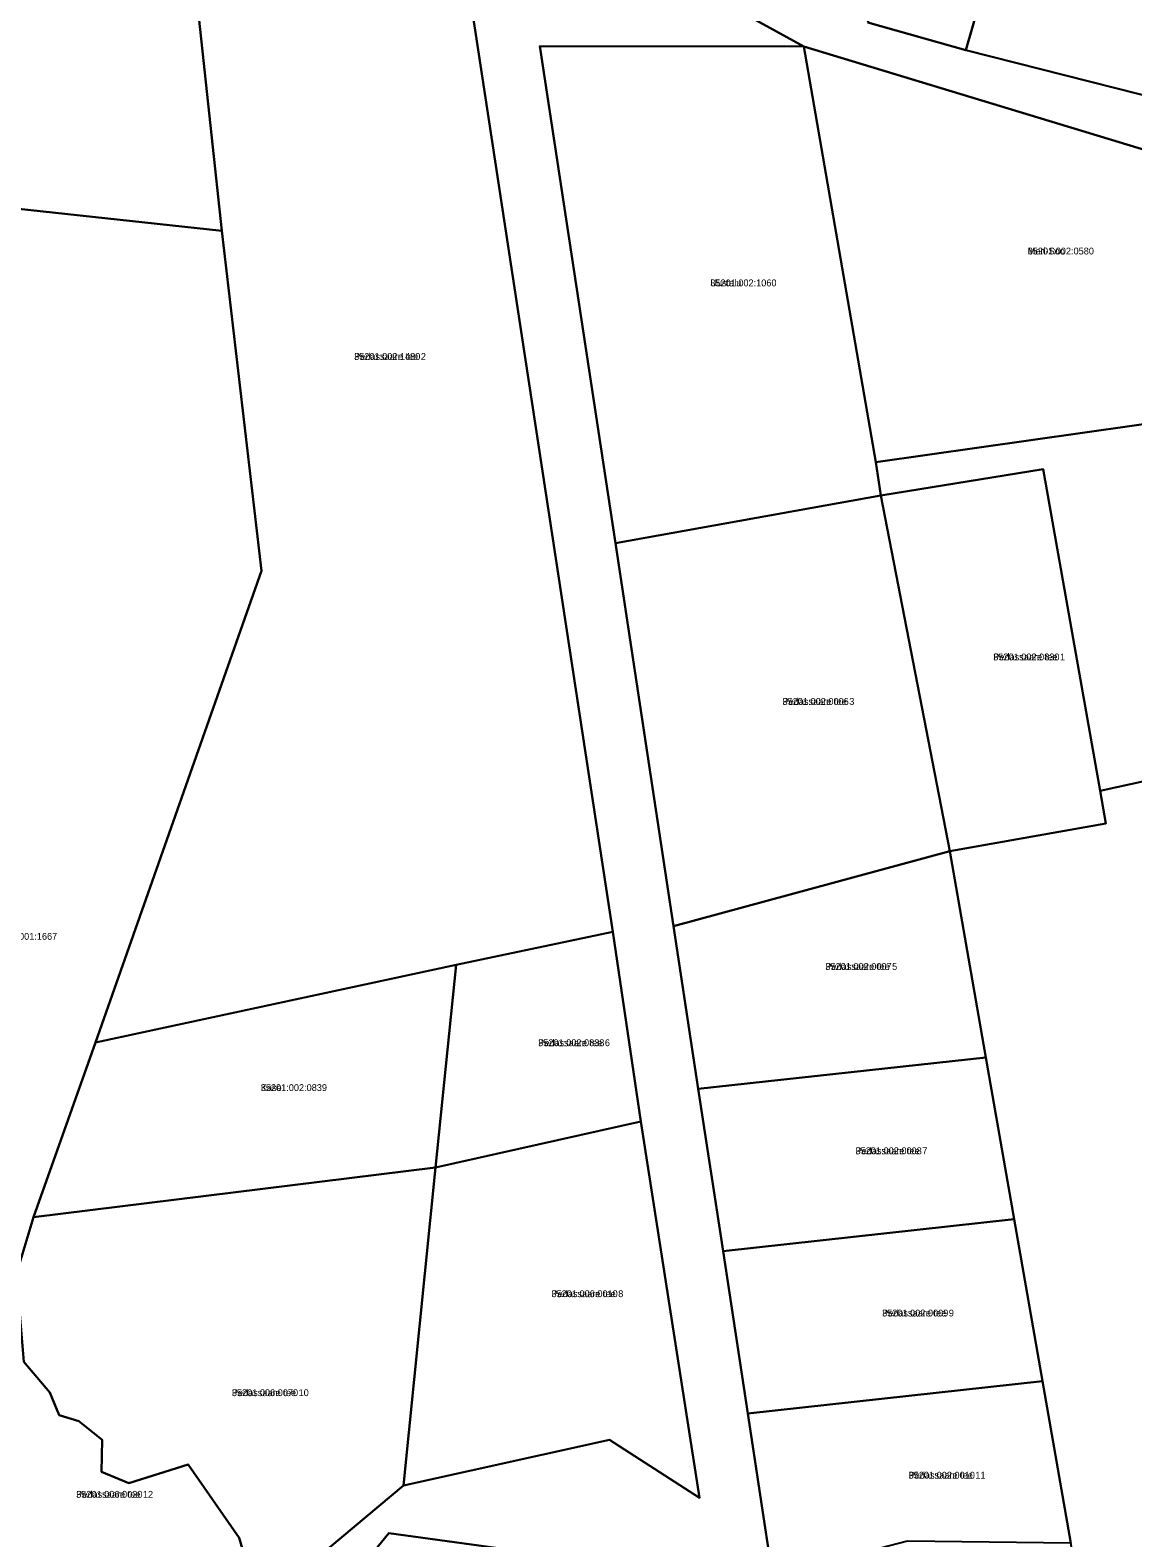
# Model space of a CAD drawing. Extents: x 570181 to 611446, y 6571894 to 6617855.
# Drawn here: x 577948.3 to 578189.7, y 6595335.2 to 6595665.4 of the extents above; entities that cross this region are included whole.
import ezdxf

# ---------------------------------------------------------------- set-up
doc = ezdxf.new("R2010")
doc.units = 0
for name, color, linetype in [('L_AADRESS', 7, 'Continuous'), ('PIIR', 7, 'Continuous'), ('TUNNUS', 7, 'Continuous')]:
    doc.layers.add(name, color=color, linetype=linetype)

msp = doc.modelspace()

# ---------------------------------------------------------------- linework, layer by layer
at = {"layer": 'PIIR'}
for points in [[(578216.83, 6595631.74), (578117.67, 6595661.8), (578081.11, 6595681.98), (578038.26, 6595714.25), (577974.41, 6595768.66), (577930.43, 6595801.29), (577928.72, 6595802.62), (577920.17, 6595809.06), (577894.55, 6595827.85), (577880.98, 6595837.16), (577870.18, 6595848.73), (577867.89, 6595872.92), (577865.75, 6595895.54), (577843.97, 6595910.68), (577820.36, 6595917.54), (577733.64, 6595893.99), (577721.38, 6595888.42), (577687.37, 6595877.16), (577647.82, 6595864.06), (577588.47, 6595844.73), (577572.36, 6595837.25), (577549.75, 6595822.32), (577498.24, 6595773.84)], [(577994.88, 6595317.19), (578029.99, 6595346.63), (578075.14, 6595356.67), (578094.86, 6595343.94), (578081.99, 6595426.34), (578075.84, 6595467.88), (578038.26, 6595714.25), (578081.11, 6595681.98), (578117.67, 6595661.8), (578059.86, 6595661.87), (578076.41, 6595553.05), (578089.17, 6595469.15), (578094.58, 6595433.56), (578099.99, 6595397.97), (578105.41, 6595362.38), (578110.82, 6595326.79)], [(578131.72, 6595667.05), (578153.17, 6595660.99), (578212.78, 6595645.94)], [(578057.71, 6595331.95), (578026.84, 6595336.22), (578013.61, 6595320.02)]]:
    msp.add_lwpolyline(points, dxfattribs=at)
for points in [[(577920.87, 6595730.6), (577930.43, 6595801.29), (577974.41, 6595768.66), (577983.04, 6595688.73), (577990.2, 6595621.44), (577945.05, 6595626.35), (577908.46, 6595630.8), (577913.81, 6595673.54)], [(578131.72, 6595667.05), (578148.29, 6595718.28), (578169.85, 6595784.92), (578187.13, 6595779.05), (578153.17, 6595660.99)], [(578187.13, 6595779.05), (578253.52, 6595762.15), (578212.78, 6595645.94), (578153.17, 6595660.99)], [(578038.26, 6595714.25), (578075.84, 6595467.88), (578041.54, 6595460.66), (577962.56, 6595443.69), (577998.9, 6595546.97), (577990.2, 6595621.44), (577983.04, 6595688.73), (577974.41, 6595768.66)], [(578133.45, 6595570.76), (578134.56, 6595563.46), (578076.41, 6595553.05), (578059.86, 6595661.87), (578117.67, 6595661.8)], [(578133.45, 6595570.76), (578117.67, 6595661.8), (578216.83, 6595631.74), (578206.22, 6595628.34), (578210.58, 6595596.85), (578212.64, 6595582)], [(577945.05, 6595626.35), (577990.2, 6595621.44), (577998.9, 6595546.97), (577962.56, 6595443.69), (577948.98, 6595405.42), (577945.23, 6595392.98), (577933.53, 6595361.55), (577880.45, 6595401.84), (577889.84, 6595437.84), (577897.44, 6595466.98), (577905.06, 6595496.13), (577914.52, 6595532.37), (577919.93, 6595553.02), (577943.86, 6595554.56), (577944.18, 6595570.61), (577944.62, 6595593.26)], [(578183.8, 6595491.66), (578182.62, 6595498.81), (578209.81, 6595504.8), (578212.64, 6595582), (578210.58, 6595596.85), (578216.75, 6595582.57), (578281.08, 6595110.55), (578213.63, 6595120.3), (578207.94, 6595152.81), (578202.25, 6595185.31), (578196.56, 6595217.81), (578187.24, 6595271.01), (578176.2, 6595334.05), (578169.99, 6595369.51), (578163.78, 6595404.97), (578157.57, 6595440.42), (578149.65, 6595485.57)], [(578170.11, 6595569.24), (578134.56, 6595563.46), (578133.45, 6595570.76), (578212.64, 6595582), (578209.81, 6595504.8), (578182.62, 6595498.81)], [(578134.56, 6595563.46), (578170.11, 6595569.24), (578182.62, 6595498.81), (578183.8, 6595491.66), (578149.65, 6595485.57)], [(578076.41, 6595553.05), (578134.56, 6595563.46), (578149.65, 6595485.57), (578089.17, 6595469.15)], [(578094.58, 6595433.56), (578089.17, 6595469.15), (578149.65, 6595485.57), (578157.56, 6595440.42)], [(578075.84, 6595467.88), (578081.99, 6595426.34), (578037.03, 6595416.26), (578041.54, 6595460.66)], [(578041.54, 6595460.66), (578037.03, 6595416.26), (577948.98, 6595405.42), (577962.56, 6595443.69)], [(578094.58, 6595433.56), (578157.56, 6595440.42), (578163.77, 6595404.97), (578099.99, 6595397.97)], [(578037.03, 6595416.26), (578081.99, 6595426.34), (578094.86, 6595343.94), (578075.14, 6595356.67), (578029.99, 6595346.63)], [(577993.74, 6595326.49), (577995.65, 6595329.74), (577994.04, 6595335.15), (577982.85, 6595351.25), (577969.86, 6595347.14), (577963.89, 6595349.63), (577964, 6595356.62), (577958.91, 6595360.76), (577954.63, 6595362.06), (577952.57, 6595367), (577946.88, 6595373.74), (577945.23, 6595392.98), (577948.98, 6595405.42), (578037.03, 6595416.26), (578029.99, 6595346.63), (577994.88, 6595317.19), (577991.74, 6595316.18)], [(578163.77, 6595404.97), (578169.98, 6595369.51), (578105.41, 6595362.38), (578099.99, 6595397.97)], [(577927, 6595294.95), (577918.68, 6595306.69), (577933.53, 6595361.55), (577945.23, 6595392.98), (577946.88, 6595373.74), (577952.57, 6595367), (577954.63, 6595362.06), (577958.91, 6595360.76), (577964, 6595356.62), (577963.89, 6595349.63), (577969.86, 6595347.14), (577982.85, 6595351.25), (577994.04, 6595335.15), (577995.65, 6595329.74), (577993.74, 6595326.49), (577991.74, 6595316.18)], [(578110.82, 6595326.79), (578105.41, 6595362.38), (578169.98, 6595369.51), (578176.19, 6595334.05), (578140.42, 6595334.44)], [(578024.35, 6595288.75), (578000.55, 6595295.47), (577991.93, 6595310), (577994.94, 6595310.54), (578013.61, 6595320.02), (578026.84, 6595336.22), (578057.71, 6595331.95), (578045.05, 6595293.14), (578044.28, 6595290.76)]]:
    msp.add_lwpolyline(points, close=True, dxfattribs=at)

# ---------------------------------------------------------------- texts
at = {"layer": 'L_AADRESS'}
for s, p in [('Meri-Soo', (578166.72, 6595616.28)), ('Uustalu', (578097.21, 6595609.3)), ('Pedassaare tee 2', (578019.2, 6595593.18)), ('Pedassaare tee 1', (578159.18, 6595527.37)), ('Pedassaare tee 3', (578113.03, 6595517.62)), ('Pedassaare tee 5', (578122.42, 6595459.57)), ('Pedassaare tee 6', (578059.51, 6595442.87)), ('Kase', (577998.76, 6595433.04)), ('Pedassaare tee 7', (578129.02, 6595419.2)), ('Pedassaare tee 8', (578062.43, 6595387.9)), ('Pedassaare tee 9', (578134.83, 6595383.67)), ('Pedassaare tee 10', (577992.43, 6595366.22)), ('Pedassaare tee 11', (578140.65, 6595348.15)), ('Pedassaare tee 12', (577958.34, 6595343.96))]:
    msp.add_text(s, height=1.5, dxfattribs=at).set_placement(p)
at = {"layer": 'TUNNUS'}
for s, p in [('35201:002:0580', (578166.72, 6595616.28)), ('35201:002:1060', (578097.21, 6595609.3)), ('35201:002:1480', (578019.2, 6595593.18)), ('35201:002:0830', (578159.18, 6595527.37)), ('35201:002:0006', (578113.03, 6595517.62)), ('35301:001:1667', (577939.68, 6595466.17)), ('35201:002:0007', (578122.42, 6595459.57)), ('35201:002:0838', (578059.51, 6595442.87)), ('35201:002:0839', (577998.76, 6595433.04)), ('35201:002:0008', (578129.02, 6595419.2)), ('35201:006:0010', (578062.43, 6595387.9)), ('35201:002:0009', (578134.83, 6595383.67)), ('35201:006:0070', (577992.43, 6595366.22)), ('35201:002:0010', (578140.65, 6595348.15)), ('35201:006:0020', (577958.34, 6595343.96))]:
    msp.add_text(s, height=1.5, dxfattribs=at).set_placement(p)

doc.saveas('drawing.dxf')
